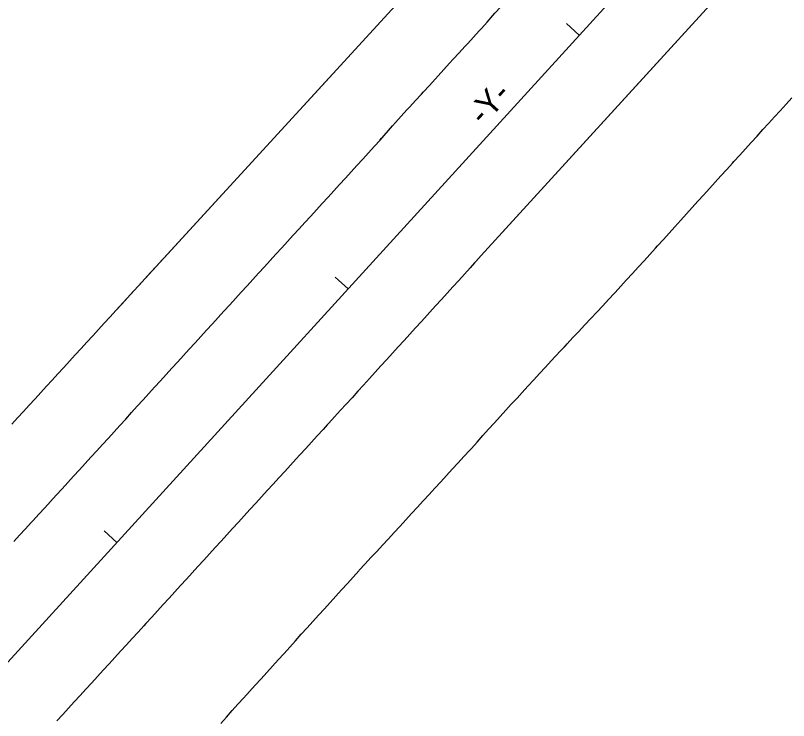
# Model space of a CAD drawing. Extents: x 1807040 to 1808827, y 913493 to 915218.
# Drawn here: x 1807478.3 to 1807703.5, y 914236.2 to 914441.7 of the extents above; entities that cross this region are included whole.
import ezdxf

# ---------------------------------------------------------------- set-up
doc = ezdxf.new("R2010")
doc.units = 0
for name, color, linetype in [('Prop EOT', 7, 'Continuous'), ('Prop Horizontal Alignment Direction Label', 7, 'Continuous'), ('Prop Horizontal Alignment Tick Small', 7, 'Continuous'), ('Scratch_Level_0', 7, 'Continuous'), ('Scratch_Level_3', 7, 'Continuous')]:
    doc.layers.add(name, color=color, linetype=linetype)

msp = doc.modelspace()

# ---------------------------------------------------------------- linework, layer by layer
at = {"layer": 'Prop EOT'}
msp.add_line((1807613.95, 914371.74), (1808063.17, 914864.38), dxfattribs=at)
for points in [[(1807601.83, 914458.72), (1807507.53, 914355.72), (1807505.84, 914353.87), (1807504.15, 914352.03), (1807502.46, 914350.19), (1807500.78, 914348.34), (1807499.09, 914346.5), (1807497.4, 914344.65), (1807495.71, 914342.81), (1807494.02, 914340.97), (1807492.34, 914339.12), (1807490.65, 914337.28), (1807488.96, 914335.43), (1807487.37, 914333.69), (1807485.68, 914331.85), (1807483.99, 914330.01), (1807482.3, 914328.16), (1807480.61, 914326.32), (1807478.92, 914324.48), (1807477.23, 914322.63)], [(1807584.48, 914405.4), (1807588.14, 914409.58), (1807588.96, 914410.48), (1807590.64, 914412.33), (1807592.32, 914414.18), (1807593.16, 914415.1), (1807594.85, 914416.94), (1807596.54, 914418.78), (1807597.18, 914419.48), (1807598.87, 914421.32), (1807600.56, 914423.16), (1807601.39, 914424.06), (1807603.06, 914425.92), (1807604.73, 914427.78), (1807605.8, 914428.97), (1807607.49, 914430.81), (1807609.17, 914432.66), (1807610.01, 914433.57), (1807611.69, 914435.41), (1807613.37, 914437.26), (1807613.99, 914437.93), (1807615.66, 914439.79), (1807617.33, 914441.65), (1807617.95, 914442.33)], [(1807644.07, 914351.48), (1807645.97, 914353.44), (1807647.66, 914355.28), (1807649.35, 914357.12), (1807651.05, 914358.96), (1807652.74, 914360.8), (1807652.92, 914361.01), (1807654.61, 914362.85), (1807656.3, 914364.7), (1807657.98, 914366.54), (1807659.67, 914368.39), (1807661.36, 914370.23), (1807663.05, 914372.08), (1807664.73, 914373.92), (1807665.33, 914374.58), (1807667.01, 914376.43), (1807668.68, 914378.29), (1807670.36, 914380.15), (1807672.04, 914382), (1807673.71, 914383.86), (1807675.39, 914385.71), (1807677.06, 914387.57), (1807678.74, 914389.42), (1807680.41, 914391.28), (1807682.09, 914393.14), (1807683.76, 914394.99), (1807685.44, 914396.85), (1807687.11, 914398.7), (1807687.55, 914399.18), (1807689.23, 914401.03), (1807690.92, 914402.88), (1807692.6, 914404.72), (1807694.29, 914406.57), (1807695.97, 914408.42), (1807697.66, 914410.26), (1807699.34, 914412.11), (1807701.03, 914413.95), (1807702.72, 914415.8), (1807704.4, 914417.65)], [(1807477.8, 914288.37), (1807479.49, 914290.22), (1807481.18, 914292.06), (1807482.87, 914293.91), (1807483.44, 914294.54), (1807485.13, 914296.39), (1807486.81, 914298.23), (1807488.5, 914300.08), (1807490.18, 914301.93), (1807491.86, 914303.78), (1807493.55, 914305.62), (1807495.23, 914307.47), (1807496.92, 914309.32), (1807498.6, 914311.17), (1807500.28, 914313.02), (1807501.97, 914314.86), (1807503.65, 914316.71), (1807505.34, 914318.56), (1807507.02, 914320.41), (1807508.7, 914322.25), (1807510.39, 914324.1), (1807512.07, 914325.95), (1807513.75, 914327.8), (1807515.44, 914329.65), (1807517.12, 914331.49), (1807518.81, 914333.34), (1807520.49, 914335.19), (1807522.17, 914337.04), (1807523.86, 914338.88), (1807525.54, 914340.73), (1807527.23, 914342.58), (1807528.91, 914344.43), (1807530.59, 914346.28), (1807532.28, 914348.12), (1807533.96, 914349.97), (1807535.65, 914351.82), (1807537.33, 914353.67), (1807539.01, 914355.51), (1807540.7, 914357.36), (1807542.38, 914359.21), (1807544.07, 914361.06), (1807545.75, 914362.91), (1807547.43, 914364.75), (1807549.12, 914366.6), (1807550.8, 914368.45), (1807552.49, 914370.3), (1807554.17, 914372.14), (1807555.85, 914373.99), (1807557.54, 914375.84), (1807559.22, 914377.69), (1807560.91, 914379.54), (1807562.59, 914381.38), (1807564.27, 914383.23), (1807565.96, 914385.08), (1807567.64, 914386.93), (1807569.33, 914388.77), (1807571.01, 914390.62), (1807572.69, 914392.47), (1807574.38, 914394.32), (1807576.06, 914396.17), (1807577.74, 914398.01), (1807579.43, 914399.86), (1807581.11, 914401.71), (1807582.8, 914403.56), (1807584.48, 914405.4), (1807584.54, 914405.47), (1807584.92, 914405.91)], [(1807613.95, 914371.74), (1807612.41, 914370.03), (1807610.73, 914368.18), (1807609.05, 914366.32), (1807607.38, 914364.47), (1807605.7, 914362.61), (1807604.02, 914360.76), (1807602.35, 914358.91), (1807600.67, 914357.05), (1807598.99, 914355.2), (1807598.21, 914354.33), (1807596.53, 914352.48), (1807594.84, 914350.64), (1807593.16, 914348.79), (1807591.47, 914346.94), (1807589.79, 914345.1), (1807588.1, 914343.25), (1807586.42, 914341.4), (1807584.73, 914339.55), (1807583.05, 914337.71), (1807581.36, 914335.86), (1807579.68, 914334.01), (1807577.99, 914332.17), (1807576.31, 914330.32), (1807574.62, 914328.47), (1807572.94, 914326.63), (1807571.25, 914324.78), (1807569.57, 914322.93), (1807567.88, 914321.09), (1807566.2, 914319.24), (1807564.51, 914317.39), (1807562.83, 914315.55), (1807561.14, 914313.7), (1807560.06, 914312.52), (1807558.38, 914310.67), (1807556.7, 914308.82), (1807555.01, 914306.97), (1807553.33, 914305.13), (1807551.64, 914303.28), (1807549.96, 914301.43), (1807548.27, 914299.58), (1807546.59, 914297.74), (1807544.91, 914295.89), (1807543.22, 914294.04), (1807541.54, 914292.19), (1807539.85, 914290.35), (1807538.17, 914288.5), (1807536.48, 914286.65), (1807534.8, 914284.8), (1807533.12, 914282.96), (1807531.43, 914281.11), (1807529.75, 914279.26), (1807528.06, 914277.41), (1807526.38, 914275.57), (1807524.7, 914273.72), (1807523.01, 914271.87), (1807521.33, 914270.02), (1807519.64, 914268.18), (1807517.96, 914266.33), (1807516.27, 914264.48), (1807515.67, 914263.82), (1807513.98, 914261.97), (1807512.3, 914260.13), (1807510.61, 914258.28), (1807508.92, 914256.44), (1807507.23, 914254.59), (1807505.55, 914252.74), (1807503.86, 914250.9), (1807502.17, 914249.05), (1807500.49, 914247.21), (1807498.8, 914245.36), (1807497.11, 914243.52), (1807495.43, 914241.67), (1807493.74, 914239.83), (1807492.05, 914237.98), (1807490.37, 914236.14)], [(1807538.06, 914235.41), (1807539.74, 914237.26), (1807541.42, 914239.12), (1807543.1, 914240.97), (1807544.77, 914242.82), (1807546.45, 914244.68), (1807548.13, 914246.53), (1807549.81, 914248.38), (1807551.48, 914250.24), (1807553.16, 914252.09), (1807554.84, 914253.94), (1807556.52, 914255.8), (1807558.19, 914257.65), (1807559.87, 914259.51), (1807561.55, 914261.36), (1807563.23, 914263.21), (1807564.91, 914265.07), (1807566.58, 914266.92), (1807568.26, 914268.77), (1807569.94, 914270.63), (1807571.62, 914272.48), (1807573.29, 914274.33), (1807574.97, 914276.19), (1807576.65, 914278.04), (1807578.33, 914279.9), (1807578.44, 914280.02), (1807580.14, 914281.86), (1807581.83, 914283.7), (1807583.52, 914285.54), (1807585.21, 914287.38), (1807586.91, 914289.22), (1807588.6, 914291.06), (1807590.29, 914292.9), (1807591.98, 914294.74), (1807593.67, 914296.59), (1807595.37, 914298.43), (1807597.06, 914300.27), (1807598.75, 914302.11), (1807600.44, 914303.95), (1807602.14, 914305.79), (1807603.83, 914307.63), (1807605.52, 914309.47), (1807607.21, 914311.31), (1807608.91, 914313.15), (1807610.6, 914314.99), (1807611.09, 914315.54), (1807612.77, 914317.39), (1807614.44, 914319.25), (1807616.11, 914321.11), (1807617.79, 914322.96), (1807619.46, 914324.82), (1807621.13, 914326.68), (1807622.69, 914328.38), (1807624.38, 914330.22), (1807625.88, 914331.86), (1807627.57, 914333.7), (1807629.26, 914335.54), (1807630.95, 914337.38), (1807632.64, 914339.22), (1807634.33, 914341.06), (1807635.53, 914342.35), (1807637.24, 914344.17), (1807638.95, 914346), (1807640.65, 914347.83), (1807642.36, 914349.65), (1807644.07, 914351.48)], [(1807538.06, 914235.41), (1807539.74, 914237.26), (1807541.42, 914239.12), (1807543.1, 914240.97), (1807544.77, 914242.82), (1807546.45, 914244.68), (1807548.13, 914246.53), (1807549.81, 914248.38), (1807551.48, 914250.24), (1807553.16, 914252.09), (1807554.84, 914253.94), (1807556.52, 914255.8), (1807558.19, 914257.65), (1807559.87, 914259.51), (1807561.55, 914261.36), (1807563.23, 914263.21), (1807564.91, 914265.07), (1807566.58, 914266.92), (1807568.26, 914268.77), (1807569.94, 914270.63), (1807571.62, 914272.48), (1807573.29, 914274.33), (1807574.97, 914276.19), (1807576.65, 914278.04), (1807578.33, 914279.9), (1807578.44, 914280.02), (1807580.14, 914281.86), (1807581.83, 914283.7), (1807583.52, 914285.54), (1807585.21, 914287.38), (1807586.91, 914289.22), (1807588.6, 914291.06), (1807590.29, 914292.9), (1807591.98, 914294.74), (1807593.67, 914296.59), (1807595.37, 914298.43), (1807597.06, 914300.27), (1807598.75, 914302.11), (1807600.44, 914303.95), (1807602.14, 914305.79), (1807603.83, 914307.63), (1807605.52, 914309.47), (1807607.21, 914311.31), (1807608.91, 914313.15), (1807610.6, 914314.99), (1807611.09, 914315.54), (1807612.77, 914317.39), (1807614.44, 914319.25), (1807616.11, 914321.11), (1807617.79, 914322.96), (1807619.46, 914324.82), (1807621.13, 914326.68), (1807622.69, 914328.38), (1807624.38, 914330.22), (1807625.88, 914331.86), (1807627.57, 914333.7), (1807629.26, 914335.54), (1807630.95, 914337.38), (1807632.64, 914339.22), (1807634.33, 914341.06), (1807635.53, 914342.35), (1807637.24, 914344.17), (1807638.95, 914346), (1807640.65, 914347.83), (1807642.36, 914349.65), (1807644.07, 914351.48)]]:
    msp.add_lwpolyline(points, dxfattribs=at)
at = {"layer": 'Prop Horizontal Alignment Tick Small'}
for p, q in [((1807642.51, 914435.97), (1807638.81, 914439.33)), ((1807575.15, 914362.06), (1807571.45, 914365.43)), ((1807507.78, 914288.15), (1807504.09, 914291.52))]:
    msp.add_line(p, q, dxfattribs=at)
at = {"layer": 'Scratch_Level_0'}
for p, q in [((1808063.17, 914864.38), (1807658.9, 914421.03)), ((1807611.69, 914435.41), (1807613.37, 914437.26)), ((1807613.37, 914437.26), (1807613.99, 914437.93)), ((1807607.49, 914430.81), (1807609.17, 914432.66)), ((1807605.8, 914428.97), (1807607.49, 914430.81)), ((1807604.73, 914427.78), (1807605.8, 914428.97)), ((1807600.56, 914423.16), (1807601.39, 914424.06)), ((1807598.87, 914421.32), (1807600.56, 914423.16)), ((1807658.9, 914421.03), (1807613.95, 914371.74)), ((1807590.64, 914412.33), (1807592.32, 914414.18)), ((1807584.92, 914405.91), (1807588.14, 914409.58)), ((1807584.91, 914405.9), (1807584.92, 914405.91)), ((1807582.8, 914403.56), (1807584.48, 914405.4)), ((1807577.74, 914398.01), (1807579.43, 914399.86)), ((1807576.06, 914396.17), (1807577.74, 914398.01)), ((1807572.69, 914392.47), (1807574.38, 914394.32)), ((1807574.38, 914394.32), (1807576.06, 914396.17)), ((1807564.27, 914383.23), (1807565.96, 914385.08)), ((1807557.54, 914375.84), (1807559.22, 914377.69)), ((1807554.17, 914372.14), (1807555.85, 914373.99)), ((1807555.85, 914373.99), (1807557.54, 914375.84)), ((1807515.97, 914364.94), (1807514.28, 914363.09)), ((1807517.66, 914366.78), (1807515.97, 914364.94)), ((1807514.28, 914363.09), (1807512.59, 914361.25)), ((1807512.59, 914361.25), (1807510.9, 914359.41)), ((1807510.9, 914359.41), (1807509.22, 914357.56)), ((1807540.7, 914357.36), (1807542.38, 914359.21)), ((1807505.84, 914353.87), (1807504.15, 914352.03)), ((1807638.45, 914345.47), (1807638.95, 914346)), ((1807525.54, 914340.73), (1807527.23, 914342.58)), ((1807492.34, 914339.12), (1807490.65, 914337.28)), ((1807490.65, 914337.28), (1807488.96, 914335.43)), ((1807520.49, 914335.19), (1807522.17, 914337.04)), ((1807518.81, 914333.34), (1807520.49, 914335.19)), ((1807485.68, 914331.85), (1807483.99, 914330.01)), ((1807483.99, 914330.01), (1807482.3, 914328.16)), ((1807513.75, 914327.8), (1807515.44, 914329.65)), ((1807512.07, 914325.95), (1807513.75, 914327.8)), ((1807478.92, 914324.48), (1807477.23, 914322.63)), ((1807510.39, 914324.1), (1807512.07, 914325.95)), ((1807507.02, 914320.41), (1807508.7, 914322.25)), ((1807508.7, 914322.25), (1807510.39, 914324.1)), ((1807496.92, 914309.32), (1807498.6, 914311.17)), ((1807488.5, 914300.08), (1807490.18, 914301.93)), ((1807490.18, 914301.93), (1807491.86, 914303.78)), ((1807486.81, 914298.23), (1807488.5, 914300.08)), ((1807479.49, 914290.22), (1807481.18, 914292.06)), ((1807477.8, 914288.37), (1807479.49, 914290.22))]:
    msp.add_line(p, q, dxfattribs=at)
for points in [[(1807601.83, 914458.72), (1807521.51, 914370.99), (1807521.03, 914370.47), (1807519.35, 914368.63), (1807517.66, 914366.78)], [(1807617.33, 914441.65), (1807617.95, 914442.33), (1807619.64, 914444.17)], [(1807613.99, 914437.93), (1807615.66, 914439.79), (1807617.33, 914441.65)], [(1807609.17, 914432.66), (1807610.01, 914433.57), (1807611.69, 914435.41)], [(1807601.39, 914424.06), (1807603.06, 914425.92), (1807604.73, 914427.78)], [(1807596.54, 914418.78), (1807597.18, 914419.48), (1807598.87, 914421.32)], [(1807592.32, 914414.18), (1807593.16, 914415.1), (1807594.85, 914416.94), (1807596.54, 914418.78)], [(1807685.44, 914396.85), (1807687.11, 914398.7), (1807687.55, 914399.18), (1807689.23, 914401.03), (1807690.92, 914402.88), (1807692.6, 914404.72), (1807694.29, 914406.57), (1807695.97, 914408.42), (1807697.66, 914410.26), (1807699.34, 914412.11), (1807701.03, 914413.95), (1807702.72, 914415.8), (1807704.4, 914417.65)], [(1807588.14, 914409.58), (1807588.96, 914410.48), (1807590.64, 914412.33)], [(1807584.48, 914405.4), (1807584.54, 914405.47), (1807584.91, 914405.9)], [(1807579.43, 914399.86), (1807581.11, 914401.71), (1807582.8, 914403.56)], [(1807644.07, 914351.48), (1807645.97, 914353.44), (1807647.66, 914355.28), (1807649.35, 914357.12), (1807651.05, 914358.96), (1807652.74, 914360.8), (1807652.92, 914361.01), (1807654.61, 914362.85), (1807656.3, 914364.7), (1807657.98, 914366.54), (1807659.67, 914368.39), (1807661.36, 914370.23), (1807663.05, 914372.08), (1807664.73, 914373.92), (1807665.33, 914374.58), (1807667.01, 914376.43), (1807668.68, 914378.29), (1807670.36, 914380.15), (1807672.04, 914382), (1807673.71, 914383.86), (1807675.39, 914385.71), (1807677.06, 914387.57), (1807678.74, 914389.42), (1807680.41, 914391.28), (1807682.09, 914393.14), (1807683.76, 914394.99), (1807685.44, 914396.85)], [(1807565.96, 914385.08), (1807567.64, 914386.93), (1807569.33, 914388.77), (1807571.01, 914390.62), (1807572.69, 914392.47)], [(1807559.22, 914377.69), (1807560.91, 914379.54), (1807562.59, 914381.38), (1807564.27, 914383.23)], [(1807550.8, 914368.45), (1807552.49, 914370.3), (1807554.17, 914372.14)], [(1807613.95, 914371.74), (1807612.41, 914370.03), (1807612, 914369.58)], [(1807612, 914369.58), (1807610.73, 914368.18), (1807609.05, 914366.32), (1807607.38, 914364.47), (1807605.7, 914362.61), (1807604.02, 914360.76), (1807602.35, 914358.91), (1807600.67, 914357.05), (1807598.99, 914355.2), (1807598.21, 914354.33), (1807596.53, 914352.48), (1807594.84, 914350.64), (1807593.16, 914348.79), (1807591.47, 914346.94), (1807589.79, 914345.1), (1807588.1, 914343.25), (1807586.42, 914341.4), (1807584.73, 914339.55), (1807583.05, 914337.71), (1807581.36, 914335.86), (1807579.68, 914334.01), (1807577.99, 914332.17), (1807576.31, 914330.32), (1807574.62, 914328.47), (1807572.94, 914326.63), (1807571.25, 914324.78), (1807569.57, 914322.93), (1807569.07, 914322.39)], [(1807547.43, 914364.75), (1807549.12, 914366.6), (1807550.8, 914368.45)], [(1807542.38, 914359.21), (1807544.07, 914361.06), (1807545.75, 914362.91), (1807547.43, 914364.75)], [(1807509.22, 914357.56), (1807507.53, 914355.72), (1807505.84, 914353.87)], [(1807537.33, 914353.67), (1807539.01, 914355.51), (1807540.7, 914357.36)], [(1807530.59, 914346.28), (1807532.28, 914348.12), (1807533.96, 914349.97), (1807535.65, 914351.82), (1807537.33, 914353.67)], [(1807504.15, 914352.03), (1807502.46, 914350.19), (1807500.78, 914348.34), (1807499.09, 914346.5)], [(1807638.95, 914346), (1807640.65, 914347.83), (1807642.36, 914349.65), (1807644.07, 914351.48)], [(1807499.09, 914346.5), (1807497.4, 914344.65), (1807495.71, 914342.81)], [(1807527.23, 914342.58), (1807528.91, 914344.43), (1807530.59, 914346.28)], [(1807595.37, 914298.43), (1807597.06, 914300.27), (1807598.75, 914302.11), (1807600.44, 914303.95), (1807602.14, 914305.79), (1807603.83, 914307.63), (1807605.52, 914309.47), (1807607.21, 914311.31), (1807608.91, 914313.15), (1807610.6, 914314.99), (1807611.09, 914315.54), (1807612.77, 914317.39), (1807614.44, 914319.25), (1807616.11, 914321.11), (1807617.79, 914322.96), (1807619.46, 914324.82), (1807621.13, 914326.68), (1807622.69, 914328.38), (1807624.38, 914330.22), (1807625.88, 914331.86), (1807627.57, 914333.7), (1807629.26, 914335.54), (1807630.95, 914337.38), (1807632.64, 914339.22), (1807634.33, 914341.06), (1807635.53, 914342.35), (1807637.24, 914344.17), (1807638.45, 914345.47)], [(1807495.71, 914342.81), (1807494.02, 914340.97), (1807492.34, 914339.12)], [(1807522.17, 914337.04), (1807523.86, 914338.88), (1807525.54, 914340.73)], [(1807488.96, 914335.43), (1807487.37, 914333.69), (1807485.68, 914331.85)], [(1807515.44, 914329.65), (1807517.12, 914331.49), (1807518.81, 914333.34)], [(1807482.3, 914328.16), (1807480.61, 914326.32), (1807478.92, 914324.48)], [(1807569.07, 914322.39), (1807567.88, 914321.09), (1807566.2, 914319.24), (1807564.51, 914317.39), (1807562.83, 914315.55), (1807561.14, 914313.7), (1807560.06, 914312.52), (1807558.38, 914310.67), (1807556.7, 914308.82), (1807555.01, 914306.97), (1807553.33, 914305.13), (1807551.64, 914303.28), (1807549.96, 914301.43), (1807548.27, 914299.58), (1807546.59, 914297.74), (1807544.91, 914295.89), (1807543.22, 914294.04), (1807541.54, 914292.19), (1807539.85, 914290.35), (1807538.17, 914288.5), (1807536.48, 914286.65), (1807534.8, 914284.8), (1807533.12, 914282.96), (1807531.43, 914281.11), (1807529.75, 914279.26), (1807528.06, 914277.41), (1807526.38, 914275.57), (1807524.7, 914273.72), (1807523.01, 914271.87), (1807521.33, 914270.02), (1807519.64, 914268.18), (1807517.96, 914266.33), (1807516.27, 914264.48), (1807515.67, 914263.82), (1807513.98, 914261.97), (1807512.3, 914260.13), (1807510.61, 914258.28), (1807508.92, 914256.44), (1807507.23, 914254.59), (1807505.55, 914252.74), (1807503.86, 914250.9), (1807502.17, 914249.05), (1807500.49, 914247.21), (1807498.8, 914245.36), (1807497.11, 914243.52), (1807495.43, 914241.67), (1807493.74, 914239.83), (1807492.05, 914237.98), (1807490.37, 914236.14)], [(1807503.65, 914316.71), (1807505.34, 914318.56), (1807507.02, 914320.41)], [(1807498.6, 914311.17), (1807500.28, 914313.02), (1807501.97, 914314.86), (1807503.65, 914316.71)], [(1807491.86, 914303.78), (1807493.55, 914305.62), (1807495.23, 914307.47), (1807496.92, 914309.32)], [(1807483.44, 914294.54), (1807485.13, 914296.39), (1807486.81, 914298.23)], [(1807538.06, 914235.41), (1807539.74, 914237.26), (1807541.42, 914239.12), (1807543.1, 914240.97), (1807544.77, 914242.82), (1807546.45, 914244.68), (1807548.13, 914246.53), (1807549.81, 914248.38), (1807551.48, 914250.24), (1807553.16, 914252.09), (1807554.84, 914253.94), (1807556.52, 914255.8), (1807558.19, 914257.65), (1807559.87, 914259.51), (1807561.55, 914261.36), (1807563.23, 914263.21), (1807564.91, 914265.07), (1807566.58, 914266.92), (1807568.26, 914268.77), (1807569.94, 914270.63), (1807571.62, 914272.48), (1807573.29, 914274.33), (1807574.97, 914276.19), (1807576.65, 914278.04), (1807578.33, 914279.9), (1807578.44, 914280.02), (1807580.14, 914281.86), (1807581.83, 914283.7), (1807583.52, 914285.54), (1807585.21, 914287.38), (1807586.91, 914289.22), (1807588.6, 914291.06), (1807590.29, 914292.9), (1807591.98, 914294.74), (1807593.67, 914296.59), (1807595.37, 914298.43)], [(1807481.18, 914292.06), (1807482.87, 914293.91), (1807483.44, 914294.54)]]:
    msp.add_lwpolyline(points, dxfattribs=at)
at = {"layer": 'Scratch_Level_3'}
msp.add_line((1807238.34, 913992.52), (1808046.68, 914879.41), dxfattribs=at)

# ---------------------------------------------------------------- texts
at = {"layer": 'Prop Horizontal Alignment Direction Label'}
msp.add_text('-Y-', height=7, rotation=47.6532, dxfattribs=at).set_placement((1807614.57, 914409.32))

doc.saveas('drawing.dxf')
